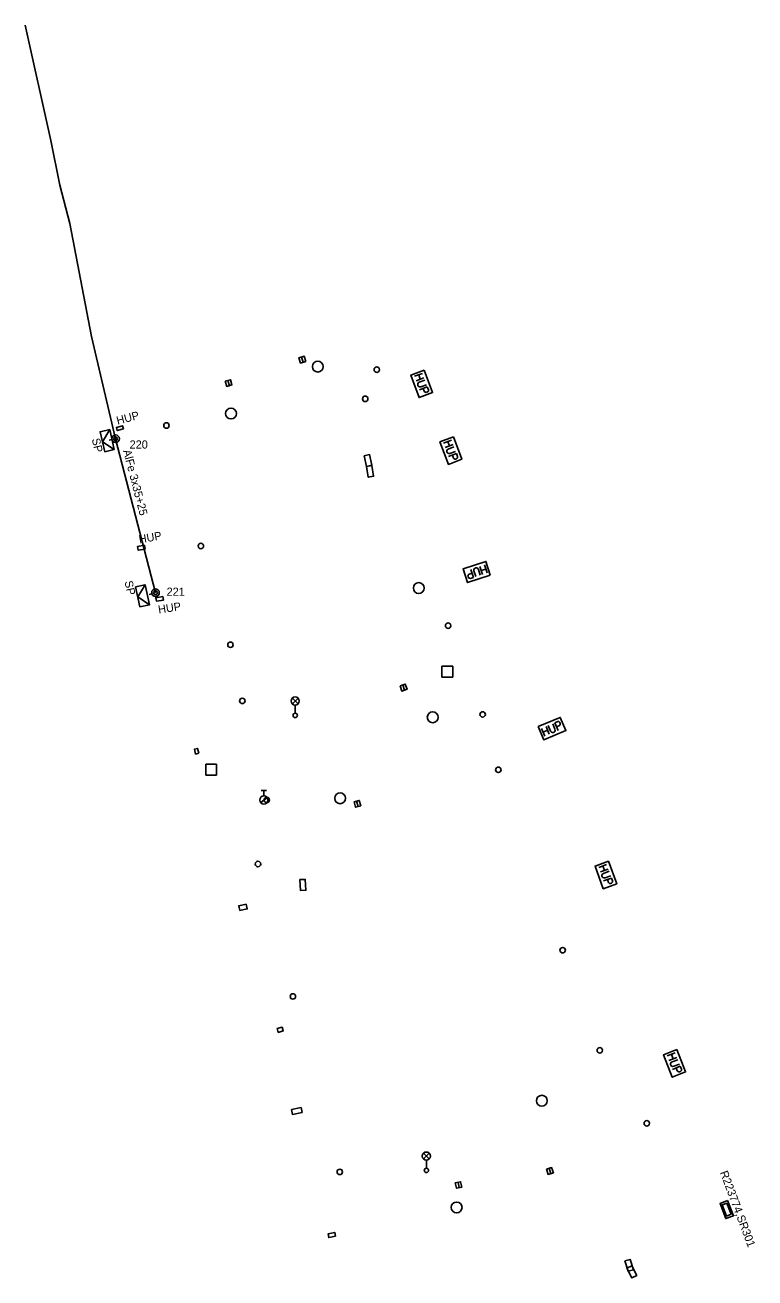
# Model space of a CAD drawing. Extents: x -577028 to -568584, y -1207664 to -1202947.
# Drawn here: x -575422.2 to -575355.1, y -1204108.2 to -1203993.1 of the extents above; entities that cross this region are included whole.
import ezdxf

# ---------------------------------------------------------------- set-up
doc = ezdxf.new("R2010")
doc.units = 0
for name, color, linetype in [('CIZÍ_NADZEM', 7, 'Continuous'), ('CIZÍ_NADZEM_POPIS', 7, 'Continuous'), ('ELE_EON', 7, 'Continuous'), ('ELE_EON_POPIS', 7, 'Continuous')]:
    doc.layers.add(name, color=color, linetype=linetype)

msp = doc.modelspace()

# ---------------------------------------------------------------- linework, layer by layer
at = {"layer": 'CIZÍ_NADZEM'}
for p, q in [((-575396.66, -1204024.04), (-575396.8, -1204023.56)), ((-575403.58, -1204025.71), (-575403.44, -1204026.19)), ((-575382.9, -1204051.98), (-575383.9, -1204051.98)), ((-575383.9, -1204051.98), (-575383.9, -1204052.98)), ((-575382.9, -1204052.98), (-575382.9, -1204051.98)), ((-575383.9, -1204052.98), (-575382.9, -1204052.98)), ((-575387.51, -1204053.69), (-575387.35, -1204054.17)), ((-575397.65, -1204055.43), (-575397.13, -1204054.9)), ((-575397.12, -1204055.43), (-575397.65, -1204054.9)), ((-575397.39, -1204055.54), (-575397.39, -1204056.29)), ((-575404.61, -1204060.97), (-575405.61, -1204060.97)), ((-575405.61, -1204060.97), (-575405.61, -1204061.97)), ((-575404.61, -1204061.97), (-575404.61, -1204060.97)), ((-575405.61, -1204061.97), (-575404.61, -1204061.97)), ((-575400.52, -1204063.4), (-575400.02, -1204063.4)), ((-575400.27, -1204063.9), (-575400.27, -1204063.4)), ((-575400.56, -1204064.5), (-575399.97, -1204064.04)), ((-575391.74, -1204064.38), (-575391.6, -1204064.86)), ((-575385.59, -1204097.25), (-575385.07, -1204096.72)), ((-575385.06, -1204097.25), (-575385.59, -1204096.72)), ((-575385.33, -1204097.36), (-575385.33, -1204098.11)), ((-575374.06, -1204098.12), (-575373.9, -1204098.6)), ((-575382.42, -1204099.41), (-575382.32, -1204099.89))]:
    msp.add_line(p, q, dxfattribs=at)
for points in [[(-575396.42, -1204023.97), (-575396.56, -1204023.49), (-575397.04, -1204023.63), (-575396.9, -1204024.11)], [(-575403.82, -1204025.78), (-575403.68, -1204026.26), (-575403.2, -1204026.12), (-575403.34, -1204025.64)], [(-575391.04, -1204032.63), (-575390.85, -1204033.61), (-575390.36, -1204033.51), (-575390.55, -1204032.53)], [(-575390.84, -1204033.62), (-575390.67, -1204034.61), (-575390.18, -1204034.52), (-575390.35, -1204033.53)], [(-575387.75, -1204053.77), (-575387.59, -1204054.25), (-575387.11, -1204054.09), (-575387.27, -1204053.61)], [(-575391.98, -1204064.45), (-575391.84, -1204064.93), (-575391.36, -1204064.79), (-575391.5, -1204064.31)], [(-575396.97, -1204071.58), (-575396.91, -1204072.58), (-575396.41, -1204072.56), (-575396.47, -1204071.56)], [(-575374.3, -1204098.2), (-575374.14, -1204098.68), (-575373.66, -1204098.52), (-575373.82, -1204098.04)], [(-575382.67, -1204099.46), (-575382.56, -1204099.95), (-575382.07, -1204099.84), (-575382.18, -1204099.35)], [(-575367.08, -1204106.63), (-575366.77, -1204107.58), (-575366.3, -1204107.43), (-575366.61, -1204106.48)], [(-575366.9, -1204107.3), (-575366.44, -1204108.19), (-575366, -1204107.96), (-575366.46, -1204107.07)]]:
    msp.add_lwpolyline(points, close=True, dxfattribs=at)
for points in [[(-575385.52, -1204024.76), (-575384.76, -1204026.83), (-575386, -1204027.28), (-575386.76, -1204025.22), (-575385.52, -1204024.76)], [(-575385.7, -1204025.06), (-575386.42, -1204025.33)], [(-575386.27, -1204025.74), (-575385.55, -1204025.48)], [(-575386.04, -1204025.19), (-575385.89, -1204025.6)], [(-575385.47, -1204025.68), (-575385.99, -1204025.87), (-575386.08, -1204025.94), (-575386.13, -1204026.03), (-575386.13, -1204026.13), (-575386.11, -1204026.19), (-575386.04, -1204026.26), (-575385.95, -1204026.3), (-575385.84, -1204026.29), (-575385.32, -1204026.1)], [(-575385.97, -1204026.57), (-575385.25, -1204026.3)], [(-575385.25, -1204026.3), (-575385.15, -1204026.57), (-575385.15, -1204026.67), (-575385.17, -1204026.72), (-575385.23, -1204026.77), (-575385.34, -1204026.81), (-575385.41, -1204026.8), (-575385.46, -1204026.78), (-575385.52, -1204026.71), (-575385.62, -1204026.44)], [(-575413.17, -1204030.16), (-575413.74, -1204030.31), (-575413.82, -1204030.02), (-575413.25, -1204029.87), (-575413.17, -1204030.16)], [(-575382.85, -1204030.9), (-575382.08, -1204032.95), (-575383.31, -1204033.42), (-575384.09, -1204031.36), (-575382.85, -1204030.9)], [(-575383.03, -1204031.2), (-575383.75, -1204031.47)], [(-575383.37, -1204031.33), (-575383.22, -1204031.74)], [(-575383.6, -1204031.88), (-575382.88, -1204031.61)], [(-575382.8, -1204031.82), (-575383.32, -1204032.01), (-575383.41, -1204032.08), (-575383.45, -1204032.17), (-575383.45, -1204032.27), (-575383.43, -1204032.33), (-575383.36, -1204032.4), (-575383.27, -1204032.43), (-575383.16, -1204032.42), (-575382.64, -1204032.23)], [(-575383.29, -1204032.7), (-575382.57, -1204032.43)], [(-575382.57, -1204032.43), (-575382.47, -1204032.7), (-575382.47, -1204032.8), (-575382.49, -1204032.84), (-575382.55, -1204032.9), (-575382.65, -1204032.94), (-575382.73, -1204032.93), (-575382.77, -1204032.92), (-575382.84, -1204032.84), (-575382.94, -1204032.57)], [(-575411.19, -1204041.2), (-575411.81, -1204041.31), (-575411.87, -1204040.96), (-575411.25, -1204040.85), (-575411.19, -1204041.2)], [(-575379.46, -1204043.6), (-575381.55, -1204044.28), (-575381.96, -1204043.02), (-575379.86, -1204042.34), (-575379.46, -1204043.6)], [(-575380.41, -1204042.81), (-575380.17, -1204043.54)], [(-575379.75, -1204043.4), (-575379.99, -1204042.67)], [(-575381.01, -1204043.81), (-575381.28, -1204043.9), (-575381.38, -1204043.89), (-575381.42, -1204043.87), (-575381.47, -1204043.81), (-575381.51, -1204043.7), (-575381.5, -1204043.62), (-575381.48, -1204043.58), (-575381.4, -1204043.52), (-575381.13, -1204043.43)], [(-575381.24, -1204043.08), (-575381.01, -1204043.81)], [(-575380.38, -1204043.61), (-575380.55, -1204043.08), (-575380.61, -1204042.99), (-575380.7, -1204042.94), (-575380.8, -1204042.93), (-575380.86, -1204042.95), (-575380.94, -1204043.02), (-575380.97, -1204043.11), (-575380.97, -1204043.22), (-575380.8, -1204043.74)], [(-575379.86, -1204043.06), (-575380.28, -1204043.19)], [(-575409.57, -1204045.58), (-575409.5, -1204045.89), (-575410.15, -1204045.99), (-575410.2, -1204045.68), (-575409.57, -1204045.58)], [(-575375.05, -1204057.52), (-575373.02, -1204056.67), (-575372.51, -1204057.88), (-575374.53, -1204058.74), (-575375.05, -1204057.52)], [(-575374.74, -1204057.69), (-575374.44, -1204058.4)], [(-575374.6, -1204058.03), (-575374.19, -1204057.85)], [(-575374.03, -1204058.23), (-575374.33, -1204057.52)], [(-575374.13, -1204057.43), (-575373.91, -1204057.94), (-575373.84, -1204058.03), (-575373.75, -1204058.07), (-575373.65, -1204058.07), (-575373.6, -1204058.04), (-575373.52, -1204057.97), (-575373.49, -1204057.88), (-575373.51, -1204057.77), (-575373.72, -1204057.26)], [(-575373.52, -1204057.18), (-575373.26, -1204057.06), (-575373.16, -1204057.06), (-575373.12, -1204057.08), (-575373.06, -1204057.14), (-575373.02, -1204057.24), (-575373.02, -1204057.32), (-575373.03, -1204057.36), (-575373.1, -1204057.43), (-575373.37, -1204057.54)], [(-575373.22, -1204057.89), (-575373.52, -1204057.18)], [(-575406.25, -1204059.96), (-575406.37, -1204059.52), (-575406.66, -1204059.6), (-575406.54, -1204060.04), (-575406.25, -1204059.96)], [(-575368.58, -1204069.9), (-575367.84, -1204071.97), (-575369.08, -1204072.42), (-575369.82, -1204070.34), (-575368.58, -1204069.9)], [(-575368.76, -1204070.2), (-575369.49, -1204070.46)], [(-575369.1, -1204070.32), (-575368.96, -1204070.74)], [(-575369.34, -1204070.88), (-575368.61, -1204070.62)], [(-575368.54, -1204070.82), (-575369.06, -1204071.01), (-575369.15, -1204071.07), (-575369.2, -1204071.16), (-575369.2, -1204071.26), (-575369.18, -1204071.32), (-575369.11, -1204071.4), (-575369.02, -1204071.43), (-575368.91, -1204071.42), (-575368.39, -1204071.24)], [(-575369.04, -1204071.7), (-575368.32, -1204071.44)], [(-575368.32, -1204071.44), (-575368.22, -1204071.71), (-575368.23, -1204071.81), (-575368.25, -1204071.85), (-575368.31, -1204071.91), (-575368.41, -1204071.94), (-575368.49, -1204071.94), (-575368.53, -1204071.92), (-575368.6, -1204071.85), (-575368.69, -1204071.58)], [(-575402.49, -1204074.42), (-575401.8, -1204074.27), (-575401.9, -1204073.84), (-575402.58, -1204073.99), (-575402.49, -1204074.42)], [(-575399.05, -1204085.28), (-575398.59, -1204085.15), (-575398.49, -1204085.49), (-575398.95, -1204085.62), (-575399.05, -1204085.28)], [(-575362.3, -1204087.21), (-575361.5, -1204089.26), (-575362.73, -1204089.74), (-575363.53, -1204087.68), (-575362.3, -1204087.21)], [(-575362.47, -1204087.51), (-575363.19, -1204087.79)], [(-575362.81, -1204087.64), (-575362.65, -1204088.06)], [(-575363.03, -1204088.2), (-575362.31, -1204087.92)], [(-575362.23, -1204088.13), (-575362.75, -1204088.33), (-575362.84, -1204088.39), (-575362.88, -1204088.48), (-575362.88, -1204088.58), (-575362.86, -1204088.64), (-575362.79, -1204088.72), (-575362.7, -1204088.75), (-575362.59, -1204088.74), (-575362.08, -1204088.54)], [(-575362.71, -1204089.02), (-575362, -1204088.74)], [(-575362, -1204088.74), (-575361.89, -1204089.01), (-575361.89, -1204089.11), (-575361.92, -1204089.15), (-575361.97, -1204089.21), (-575362.07, -1204089.25), (-575362.15, -1204089.24), (-575362.2, -1204089.23), (-575362.27, -1204089.15), (-575362.37, -1204088.89)], [(-575397.74, -1204092.72), (-575396.85, -1204092.53), (-575396.75, -1204092.98), (-575397.64, -1204093.16), (-575397.74, -1204092.72)], [(-575393.67, -1204104.34), (-575394.3, -1204104.48), (-575394.37, -1204104.15), (-575393.75, -1204104.01), (-575393.67, -1204104.34)]]:
    msp.add_lwpolyline(points, dxfattribs=at)
for centre, radius in [((-575395.31, -1204024.44), 0.5), ((-575389.89, -1204024.72), 0.25), ((-575390.95, -1204027.4), 0.25), ((-575403.29, -1204028.75), 0.5), ((-575409.22, -1204029.85), 0.25), ((-575406.06, -1204040.92), 0.25), ((-575386.03, -1204044.79), 0.5), ((-575383.33, -1204048.25), 0.25), ((-575403.34, -1204050), 0.25), ((-575402.25, -1204055.16), 0.25), ((-575397.39, -1204055.17), 0.375), ((-575397.39, -1204056.49), 0.2), ((-575384.75, -1204056.66), 0.5), ((-575380.16, -1204056.4), 0.25), ((-575378.72, -1204061.49), 0.25), ((-575393.26, -1204064.11), 0.5), ((-575400.27, -1204064.27), 0.375), ((-575400, -1204064.26), 0.25), ((-575400.81, -1204070.15), 0.25), ((-575372.8, -1204078.07), 0.25), ((-575397.6, -1204082.32), 0.25), ((-575369.39, -1204087.27), 0.25), ((-575374.72, -1204091.9), 0.5), ((-575365.07, -1204093.98), 0.25), ((-575385.33, -1204096.99), 0.375), ((-575385.33, -1204098.31), 0.2), ((-575393.29, -1204098.44), 0.25), ((-575382.55, -1204101.71), 0.5)]:
    msp.add_circle(centre, radius, dxfattribs=at)
at = {"layer": 'ELE_EON'}
for p, q in [((-575414.24, -1204031.14), (-575414.49, -1204031.19)), ((-575410.57, -1204045.31), (-575410.81, -1204045.37))]:
    msp.add_line(p, q, dxfattribs=at)
for points in [[(-575410.23, -1204045.22), (-575413.9, -1204031.07), (-575416.11, -1204021.66), (-575418.11, -1204011.28), (-575419.01, -1204007.75), (-575419.85, -1204003.66), (-575422.22, -1203993.05)], [(-575414.02, -1204032.05), (-575415.11, -1204031.34), (-575414.44, -1204030.23)], [(-575410.78, -1204046.32), (-575411.86, -1204045.59), (-575411.18, -1204044.48)]]:
    msp.add_lwpolyline(points, dxfattribs=at)
for points in [[(-575414.89, -1204032.26), (-575415.32, -1204030.43), (-575414.44, -1204030.23), (-575414.02, -1204032.05)], [(-575411.66, -1204046.51), (-575412.06, -1204044.68), (-575411.18, -1204044.48), (-575410.78, -1204046.32)], [(-575357.64, -1204101.07), (-575357.11, -1204102.48), (-575357.82, -1204102.74), (-575358.34, -1204101.34)], [(-575357.71, -1204101.31), (-575357.33, -1204102.34), (-575357.75, -1204102.5), (-575358.13, -1204101.47)]]:
    msp.add_lwpolyline(points, close=True, dxfattribs=at)
for centre, radius in [((-575413.9, -1204031.07), 0.35), ((-575413.9, -1204031.07), 0.175), ((-575410.23, -1204045.22), 0.35), ((-575410.23, -1204045.22), 0.175)]:
    msp.add_circle(centre, radius, dxfattribs=at)

# ---------------------------------------------------------------- texts
at = {"layer": 'CIZÍ_NADZEM_POPIS'}
for rotation, p in [(14.7436, (-575413.71, -1204029.78)), (10.0607, (-575411.7, -1204040.69)), (8.7461, (-575409.93, -1204047.14))]:
    msp.add_text('HUP', height=0.75, rotation=rotation, dxfattribs=at).set_placement(p)
at = {"layer": 'ELE_EON_POPIS'}
for s, rotation, p in [('SP', 283.0919, (-575416.09, -1204031.1)), ('AlFe 3x35+25', 284.5401, (-575413.22, -1204032.17)), ('SP', 282.4074, (-575413.08, -1204044.2)), ('R223774,SR301', 290.5561, (-575358.36, -1204098.5))]:
    msp.add_text(s, height=0.75, rotation=rotation, dxfattribs=at).set_placement(p)
for s, p in [('220', (-575412.61, -1204031.97)), ('221', (-575409.21, -1204045.5))]:
    msp.add_text(s, height=0.75, dxfattribs=at).set_placement(p)

doc.saveas('drawing.dxf')
